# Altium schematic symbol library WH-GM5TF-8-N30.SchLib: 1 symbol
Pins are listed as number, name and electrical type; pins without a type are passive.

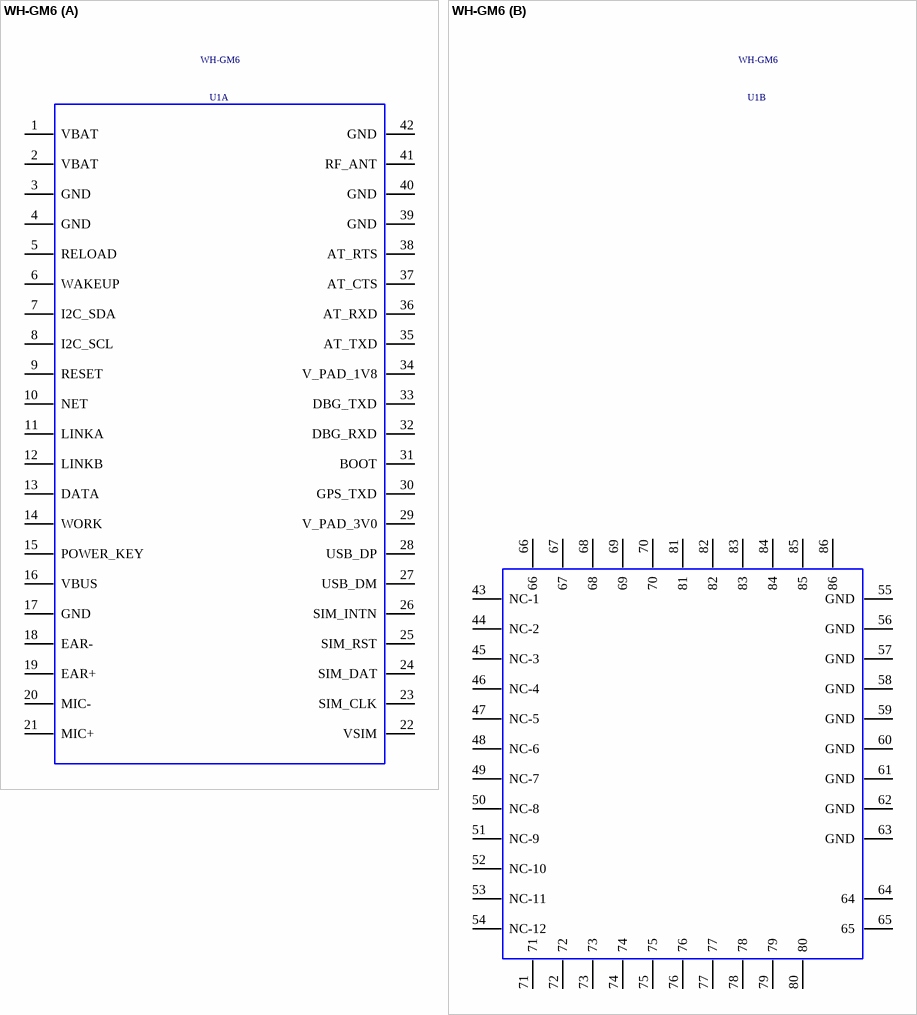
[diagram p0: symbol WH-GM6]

## WH-GM6
designator U1
footprint WH-GM6
part A pins: 1 VBAT, 2 VBAT, 3 GND, 4 GND, 5 RELOAD, 6 WAKEUP, 7 I2C_SDA, 8 I2C_SCL, 9 RESET, 10 NET, 11 LINKA, 12 LINKB, 13 DATA, 14 WORK, 15 POWER_KEY, 16 VBUS, 17 GND, 18 EAR-, 19 EAR+, 20 MIC-, 21 MIC+, 22 VSIM, 23 SIM_CLK, 24 SIM_DAT, 25 SIM_RST, 26 SIM_INTN, 27 USB_DM, 28 USB_DP, 29 V_PAD_3V0, 30 GPS_TXD, 31 BOOT, 32 DBG_RXD, 33 DBG_TXD, 34 V_PAD_1V8, 35 AT_TXD, 36 AT_RXD, 37 AT_CTS, 38 AT_RTS, 39 GND, 40 GND, 41 RF_ANT, 42 GND
part B pins: 43 NC-1, 44 NC-2, 45 NC-3, 46 NC-4, 47 NC-5, 48 NC-6, 49 NC-7, 50 NC-8, 51 NC-9, 52 NC-10, 53 NC-11, 54 NC-12, 55 GND, 56 GND, 57 GND, 58 GND, 59 GND, 60 GND, 61 GND, 62 GND, 63 GND, 64, 65, 66, 67, 68, 69, 70, 71, 72, 73, 74, 75, 76, 77, 78, 79, 80, 81, 82, 83, 84, 85, 86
